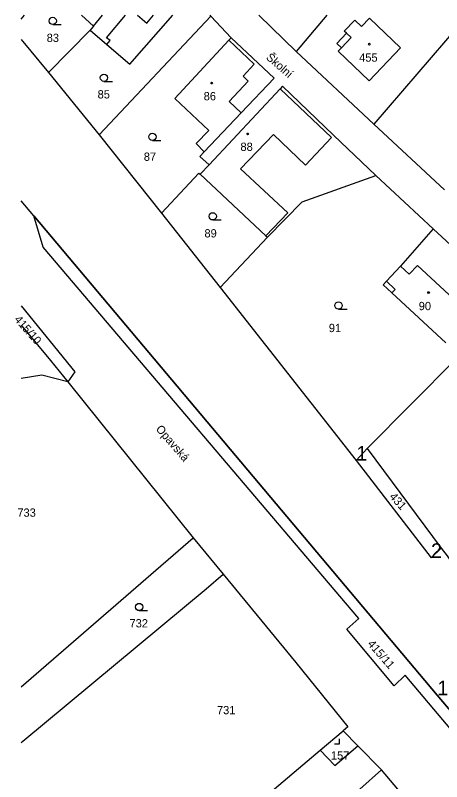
# Model space of a CAD drawing. Extents: x -504601 to -503665, y -1079870 to -1078626.
# Drawn here: x -504600.9 to -504513.3, y -1078783.7 to -1078626.2 of the extents above; entities that cross this region are included whole.
import ezdxf

# ---------------------------------------------------------------- set-up
doc = ezdxf.new("R2010")
doc.units = 0
for name, color, linetype in [('Hranice parcel', 7, 'Continuous'), ('Parcelní čísla', 7, 'Continuous'), ('Pop  PČ popisy', 7, 'Continuous'), ('Vnitřní kresba', 7, 'Continuous'), ('Vrstva 31', 7, 'Continuous'), ('Vrstva 32', 7, 'Continuous'), ('Vrstva 54', 7, 'Continuous'), ('Značky budov', 7, 'Continuous'), ('Značky kultur', 7, 'Continuous')]:
    doc.layers.add(name, color=color, linetype=linetype)

msp = doc.modelspace()

# ---------------------------------------------------------------- linework, layer by layer
at = {"layer": 'Hranice parcel'}
for p, q in [((-504599.72, -1078626.96), (-504598.99, -1078626.15)), ((-504587.33, -1078626.15), (-504584.87, -1078628.4)), ((-504583.69, -1078650.73), (-504560.74, -1078626.29)), ((-504560.74, -1078626.29), (-504560.89, -1078626.15)), ((-504556.52, -1078630.76), (-504560.74, -1078626.29)), ((-504550.86, -1078626.15), (-504543.22, -1078633.58)), ((-504536.89, -1078626.15), (-504543.22, -1078633.58)), ((-504508.05, -1078626.15), (-504527.23, -1078648.54)), ((-504584.87, -1078628.4), (-504585.52, -1078629.17)), ((-504594.06, -1078637.92), (-504585.52, -1078629.17)), ((-504599.72, -1078631.15), (-504594.06, -1078637.92)), ((-504543.22, -1078633.58), (-504527.23, -1078648.54)), ((-504594.06, -1078637.92), (-504583.69, -1078650.73)), ((-504527.23, -1078648.54), (-504512.71, -1078662.02)), ((-504583.69, -1078650.73), (-504570.88, -1078666.85)), ((-504563.74, -1078652.52), (-504562.08, -1078654.23)), ((-504561.09, -1078656.9), (-504562.9, -1078658.83)), ((-504515.01, -1078670.07), (-504526.83, -1078659.1)), ((-504570.88, -1078666.85), (-504558.84, -1078682.13)), ((-504595.19, -1078673.8), (-504597.09, -1078667.4)), ((-504515.01, -1078670.07), (-504521.74, -1078677.69)), ((-504497.46, -1078686.36), (-504515.01, -1078670.07)), ((-504558.84, -1078682.13), (-504549.08, -1078671.78)), ((-504558.84, -1078682.13), (-504530.83, -1078717.69)), ((-504528.6, -1078715.23), (-504510.4, -1078696.81)), ((-504590.14, -1078701.47), (-504564.35, -1078733.55)), ((-504530.83, -1078717.69), (-504528.6, -1078715.23)), ((-504528.6, -1078715.23), (-504513.37, -1078735.66)), ((-504564.35, -1078733.55), (-504558.23, -1078741)), ((-504513.37, -1078735.66), (-504512.16, -1078737.29)), ((-504538.29, -1078777.24), (-504533.54, -1078773.23)), ((-504533.54, -1078773.23), (-504530.49, -1078776.34)), ((-504525.66, -1078781.28), (-504530.49, -1078776.34)), ((-504599.72, -1078829.02), (-504538.29, -1078777.24)), ((-504516.36, -1078792.2), (-504525.66, -1078781.28))]:
    msp.add_line(p, q, dxfattribs=at)
for points in [[(-504585.52, -1078629.17), (-504582.12, -1078632.17), (-504577.37, -1078636.19), (-504568.57, -1078626.15)], [(-504584.87, -1078628.4), (-504582.98, -1078626.15)], [(-504533.89, -1078632.8), (-504534.81, -1078631.93), (-504532.83, -1078629.85), (-504533.33, -1078629.38), (-504531.17, -1078627.13), (-504529.78, -1078628.45), (-504528.15, -1078626.72), (-504521.75, -1078632.83), (-504528.16, -1078639.59), (-504534.56, -1078633.51), (-504533.89, -1078632.8)], [(-504556.52, -1078630.76), (-504557, -1078631.27), (-504568.1, -1078643.27)], [(-504562.08, -1078654.23), (-504554.47, -1078646.21), (-504547.69, -1078639.08), (-504556.52, -1078630.76)], [(-504526.83, -1078659.1), (-504535.5, -1078650.8), (-504545.97, -1078640.71), (-504546.48, -1078641.26), (-504561.09, -1078656.9)], [(-504568.1, -1078643.27), (-504561.12, -1078649.82), (-504563.74, -1078652.52)], [(-504561.09, -1078656.9), (-504563, -1078655.2), (-504562.08, -1078654.23)], [(-504570.88, -1078666.85), (-504563.18, -1078658.57), (-504562.9, -1078658.83)], [(-504562.9, -1078658.83), (-504549.41, -1078671.47), (-504549.08, -1078671.78)], [(-504549.08, -1078671.78), (-504541.95, -1078664.49), (-504526.83, -1078659.1)], [(-504597.09, -1078667.4), (-504599.72, -1078664.27)], [(-504597.09, -1078667.4), (-504514.19, -1078765.94), (-504428.7, -1078866.55), (-504382.03, -1078924.33)], [(-504382.03, -1078926.66), (-504397.6, -1078907.92), (-504520.79, -1078761.79), (-504523.08, -1078763.96), (-504532.75, -1078752.34), (-504530.29, -1078750.16), (-504595.19, -1078673.8)], [(-504521.74, -1078677.69), (-504524.65, -1078680.82), (-504525.34, -1078681.56), (-504523.53, -1078683.23), (-504512.44, -1078693.49)], [(-504599.72, -1078685.86), (-504588.66, -1078699.42), (-504590.14, -1078701.47)], [(-504599.72, -1078689.85), (-504593.67, -1078697.08), (-504590.14, -1078701.47)], [(-504590.14, -1078701.47), (-504595.47, -1078700.11), (-504599.72, -1078700.82)], [(-504530.83, -1078717.69), (-504515.48, -1078737.7), (-504513.37, -1078735.66)], [(-504599.72, -1078764.2), (-504564.35, -1078733.55)], [(-504599.72, -1078775.67), (-504599.34, -1078775.34), (-504561.66, -1078744.08), (-504558.23, -1078741)], [(-504558.23, -1078741), (-504543.24, -1078759.21), (-504532.57, -1078772.41), (-504533.54, -1078773.23)], [(-504538.29, -1078777.24), (-504535.24, -1078780.35), (-504530.49, -1078776.34)], [(-504525.66, -1078781.28), (-504530.11, -1078785.23), (-504538.39, -1078792.59), (-504549.12, -1078804.23), (-504551.53, -1078806.79), (-504558.35, -1078814.04), (-504543.52, -1078831.19), (-504520.67, -1078807.94)]]:
    msp.add_lwpolyline(points, dxfattribs=at)
at = {"layer": 'Vnitřní kresba'}
for p, q in [((-504582.14, -1078630.76), (-504578.29, -1078626.15)), ((-504575.81, -1078626.15), (-504573.86, -1078627.78)), ((-504573.86, -1078627.78), (-504572.5, -1078626.15)), ((-504531.92, -1078630.72), (-504532.83, -1078629.85)), ((-504581.43, -1078631.35), (-504582.14, -1078630.76)), ((-504582.12, -1078632.17), (-504581.43, -1078631.35)), ((-504557, -1078631.27), (-504551.82, -1078636.18)), ((-504533.89, -1078632.8), (-504531.92, -1078630.72)), ((-504551.82, -1078636.18), (-504554.11, -1078638.67)), ((-504553.08, -1078639.67), (-504556.98, -1078643.85)), ((-504554.11, -1078638.67), (-504553.08, -1078639.67)), ((-504546.48, -1078641.26), (-504535.94, -1078651.28)), ((-504556.98, -1078643.85), (-504554.47, -1078646.21)), ((-504547.86, -1078650.67), (-504554.62, -1078657.74)), ((-504541.27, -1078656.98), (-504547.86, -1078650.67)), ((-504535.94, -1078651.28), (-504541.27, -1078656.98)), ((-504554.62, -1078657.74), (-504544.93, -1078666.76)), ((-504544.93, -1078666.76), (-504549.41, -1078671.47))]:
    msp.add_line(p, q, dxfattribs=at)
for points in [[(-504507.17, -1078687.86), (-504518.29, -1078677.57), (-504519.94, -1078679.35), (-504521.74, -1078677.69)], [(-504524.65, -1078680.82), (-504522.86, -1078682.51), (-504523.53, -1078683.23)]]:
    msp.add_lwpolyline(points, dxfattribs=at)
at = {"layer": 'Vrstva 31'}
for p, q in [((-504530.83, -1078717.69), (-504530.83, -1078717.69)), ((-504513.37, -1078735.66), (-504513.37, -1078735.66)), ((-504515.48, -1078737.7), (-504515.48, -1078737.7)), ((-504514.19, -1078765.94), (-504514.19, -1078765.94))]:
    msp.add_line(p, q, dxfattribs=at)
at = {"layer": 'Vrstva 54'}
for points in [[(-504428.7, -1078866.55), (-504514.19, -1078765.94), (-504597.09, -1078667.4)], [(-504558.84, -1078682.13), (-504530.83, -1078717.69), (-504515.48, -1078737.7), (-504513.37, -1078735.66), (-504512.16, -1078737.29), (-504507.63, -1078743.89), (-504506.21, -1078745.96), (-504510.04, -1078749.73), (-504485.94, -1078776.97), (-504483.44, -1078779.79), (-504481.39, -1078782.11), (-504435.49, -1078833.98), (-504407.21, -1078868.45)]]:
    msp.add_lwpolyline(points, dxfattribs=at)
at = {"layer": 'Značky budov'}
for centre in [(-504528.15, -1078632.08), (-504560.56, -1078640.09), (-504553.17, -1078650.53), (-504515.99, -1078683.15)]:
    msp.add_circle(centre, 0.175, dxfattribs=at)
at = {"layer": 'Značky kultur'}
for p, q in [((-504593.22, -1078628.05), (-504591.47, -1078628.05)), ((-504582.7, -1078639.73), (-504580.95, -1078639.73)), ((-504572.74, -1078651.87), (-504570.99, -1078651.87)), ((-504560.34, -1078668.22), (-504558.59, -1078668.22)), ((-504534.48, -1078686.54), (-504532.73, -1078686.54)), ((-504575.47, -1078748.53), (-504573.72, -1078748.53)), ((-504534.3, -1078775.9), (-504534.3, -1078774.9)), ((-504535.3, -1078775.9), (-504534.3, -1078775.9))]:
    msp.add_line(p, q, dxfattribs=at)
for centre in [(-504593.22, -1078627.3), (-504582.7, -1078638.98), (-504572.74, -1078651.12), (-504560.34, -1078667.47), (-504534.48, -1078685.79), (-504575.47, -1078747.78)]:
    msp.add_circle(centre, 0.75, dxfattribs=at)

# ---------------------------------------------------------------- texts
at = {"layer": 'Parcelní čísla'}
for s, p in [('83', (-504594.46, -1078631.63)), ('455', (-504530.25, -1078635.68)), ('85', (-504584, -1078643.24)), ('86', (-504562.2, -1078643.62)), ('88', (-504554.64, -1078654.02)), ('87', (-504574.51, -1078656.06)), ('89', (-504562.04, -1078671.81)), ('90', (-504518.01, -1078686.76)), ('91', (-504536.48, -1078691.27)), ('733', (-504600.49, -1078729.23)), ('732', (-504577.44, -1078751.98)), ('731', (-504559.47, -1078769.83)), ('157', (-504536.05, -1078779.15))]:
    msp.add_text(s, height=1.7, dxfattribs=at).set_placement(p)
for s, rotation, p in [('415/10', 311, (-504601.23, -1078688.75)), ('431', 312, (-504524.16, -1078725.19)), ('415/11', 311, (-504528.63, -1078755.45))]:
    msp.add_text(s, height=1.7, rotation=rotation, dxfattribs=at).set_placement(p)
at = {"layer": 'Pop  PČ popisy'}
for s, rotation, p in [('Školní', 319, (-504549.51, -1078635.02)), ('Opavská', 311, (-504572.14, -1078711.27))]:
    msp.add_text(s, height=1.7, rotation=rotation, dxfattribs=at).set_placement(p)
at = {"layer": 'Vrstva 32'}
for s, p in [('1', (-504530.83, -1078717.69)), ('2', (-504515.48, -1078737.7)), ('12', (-504514.19, -1078765.94))]:
    msp.add_text(s, height=3, dxfattribs=at).set_placement(p)

doc.saveas('drawing.dxf')
